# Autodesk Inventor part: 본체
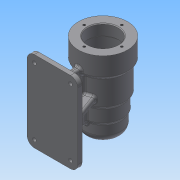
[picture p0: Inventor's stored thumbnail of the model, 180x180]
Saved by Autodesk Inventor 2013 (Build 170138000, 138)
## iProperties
Created: 2016-06
Part Number: 본체
Material: 일반
Document SubType Name: Modeling
Designer: Administrator
Density: 1 g/cm^3
Author: Administrator
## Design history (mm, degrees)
sketch "스케치1"
  geometry: C1 r 34 at (0, 0); 1 further point
  constraints: 1 centre point, 1 coincident
  dimensions: "d0" = 68 diameter of C1
extrude "돌출1" new body sketch "스케치1" distance "d1" = 28; taper "d2" = 0 deg
sketch "스케치2"
  geometry: C1 r 34 at (0, 0) reference; C2 r 30 at (0, 0)
  constraints: 1 centre point, 1 coincident
  dimensions: "d3" = 60 diameter of C2
extrude "돌출2" join sketch "스케치2" distance "d4" = 39; taper "d5" = 0 deg
sketch "스케치3"
  geometry: C1 r 30 at (0, 0) reference; C2 r 27 at (0, 0)
  constraints: 1 centre point, 1 coincident
  dimensions: "d6" = 54 diameter of C2
extrude "돌출3" join sketch "스케치3" distance "d7" = 20; taper "d8" = 0 deg
sketch "스케치4"
  geometry: C1 r 27 at (0, 0) reference; C2 r 25 at (0, 0)
  constraints: 1 centre point, 1 coincident
  dimensions: "d9" = 50 diameter of C2
extrude "돌출4" join sketch "스케치4" distance "d10" = 25; taper "d11" = 0 deg
hole "구멍1" diameter "d14" = 42; stored, may be unused: countersink angle "d18" = 90 deg, drill point angle "d20" = 0 deg; dims "d12" = 10, "d13" = 10, "d15" = 6, "d16" = 4, "d17" = 2, "d19" = 15
hole "구멍2" diameter "d23" = 48; stored, may be unused: countersink angle "d27" = 90 deg, drill point angle "d29" = 0 deg; dims "d21" = 10, "d22" = 10, "d24" = 6, "d25" = 4, "d26" = 2, "d28" = 54
hole "구멍3" diameter "d32" = 42; stored, may be unused: countersink angle "d36" = 90 deg, drill point angle "d38" = 0 deg; dims "d30" = 10, "d31" = 10, "d33" = 6, "d34" = 4, "d35" = 2, "d37" = 12
hole "구멍4" diameter "d41" = 35; stored, may be unused: countersink angle "d45" = 90 deg, drill point angle "d47" = 0 deg; dims "d39" = 10, "d40" = 10, "d42" = 6, "d43" = 4, "d44" = 2, "d46" = 18
hole "구멍5" diameter "d50" = 32; stored, may be unused: countersink angle "d54" = 90 deg, drill point angle "d56" = 0 deg; dims "d48" = 10, "d49" = 10, "d51" = 6, "d52" = 4, "d53" = 2, "d55" = 4
hole "구멍6" diameter "d59" = 21; stored, may be unused: countersink angle "d63" = 90 deg, drill point angle "d65" = 0 deg; dims "d57" = 10, "d58" = 10, "d60" = 6, "d61" = 4, "d62" = 2, "d64" = 3
node "작업 평면1"
sketch "스케치5"
  geometry: L1 (-25, -112)-(25, -112) reference; L2 (-34, 0)-(34, 0) reference; L3 (27.711, -56)-(106.129, -56); L4 (-35, -112)-(35, -112); L5 (35, -112)-(35, 0); L6 (35, 0)-(-35, 0); L7 (-35, 0)-(-35, -112); L8 (-35, -112)-(35, 0); L9 (35, -112)-(-35, 0); 5 further points
  constraints: 14 end point, 5 midpoint, 2 parallel, 1 horizontal, 1 perpendicular, 1 point on line, 1 vertical alignment
  dimensions: "d69" = 56 distance between parallel lines of L3 L1; "d70" = 70 distance of L6.end L5.end; "d72" = 112 distance between parallel lines of L6 L4
extrude "돌출5" join sketch "스케치5" distance "d73" = 10; taper "d74" = 0 deg
fillet "모깎기7" dims "d133" = 3
sketch "스케치6"
  geometry: L1 (-35, 0)-(35, 0) reference; L2 (35, 0)-(35, 112) reference; L3 (4, 20)-(4, 92); L4 (4, 92)-(-4, 92); L5 (-4, 92)-(-4, 20); L6 (-4, 20)-(4, 20); L7 (4, 56)-(-4, 56); L8 (0, 92)-(0, 20); 1 further point
  constraints: 12 end point, 4 midpoint, 2 parallel, 1 perpendicular
  dimensions: "d75" = 8 distance between parallel lines of L5 L3; "d77" = 56 distance between parallel lines of L1 L7; "d79" = 20 distance between parallel lines of L1 L6; "d80" = 35 distance between parallel lines of L2 L8
extrude "돌출6" join sketch "스케치6" stored distance "d81" = 10; taper "d82" = 0 deg
node "작업 평면2"
sketch "스케치7"
  geometry: L1 (-70, 0)-(-70, 10) reference; L2 (-70, 10)-(-39, 10) reference; L3 (-39, 10)-(-39, 40.268) reference; L4 (-31, 40.268)-(-31, 10) reference; L5 (-31, 10)-(0, 10) reference; L6 (0, 10)-(0, 0) reference; L7 (0, 0)-(-70, 0) reference; L8 (-50.509, 44.32)-(-63, 10); L9 (-19.491, 44.32)-(-7, 10); C1 r 24 at (-35, 70) reference; A1 r 30 centre (-35, 70) between (-31, 40.268) and (-39, 40.268) reference; 1 further point
  constraints: 4 end point, 2 point on circle, 2 point on line
  dimensions: "d83" = 110 deg angle of L5 L9; "d84" = 110 deg angle of L2 L8 (= d83); "d85" = 7 distance from line of L8.end L1; "d86" = 7 distance from line of L9.end L6
  node "절단 모서리 투영1"
feature "리브1" dims "d87" = 1, "d88" = 8, "d89" = 0, "d90" = 0, "d91" = 1, "d92" = 1
feature "리브2" dims "d93" = 1, "d94" = 8, "d95" = 0, "d96" = 0, "d97" = 1, "d98" = 1
node "작업 평면3"
sketch "스케치8"
  geometry: L1 (60, -84)-(60, 28) reference; L2 (60, 28)-(70, 28) reference; L3 (70, 28)-(70, -84) reference; L4 (70, -84)-(60, -84) reference; L5 (16, 28)-(16, 2.657) reference; L6 (-16, 28)-(16, 28) reference; L7 (-16, 2.657)-(-16, 28) reference; L8 (0, -3)-(0, -36) reference; 5 further points
  constraints: 1 midpoint, 1 vertical alignment, 5 other
  dimensions: "d99" = 48 distance from line of L6 point (0, -20)
feature "엠보싱1" sketch "스케치8" dims "d100" = 0.5, "d101" = 0
fillet "모깎기1" dims "d102" = 10, "d114" = 0.3
sketch "스케치9"
  geometry: C1 r 21 at (0, 0) reference; 1 further point
  constraints: 1 vertical alignment
  dimensions: "d103" = 26 distance of C1.centre point (0, 26)
hole "구멍7" sketch "스케치9" at (0, 26) diameter "d104" = 3.242; stored, may be unused: countersink angle "d108" = 90 deg, drill point angle "d110" = 118 deg; dims "d105" = 8, "d106" = 4, "d107" = 2, "d109" = 11
sketch "스케치10"
  geometry: A1 r 10 centre (25, 102) between (35, 102) and (25, 112) reference; A2 r 10 centre (-25, 102) between (-25, 112) and (-35, 102) reference; A3 r 10 centre (-25, 10) between (-35, 10) and (-25, 0) reference; A4 r 10 centre (25, 10) between (25, 0) and (35, 10) reference; 5 further points
  constraints: 4 coincident
hole "구멍8" sketch "스케치10" at (25, 102), (25, 10), (-25, 10), (-25, 102) diameter "d115" = 5; stored, may be unused: countersink angle "d119" = 90 deg, drill point angle "d121" = 0 deg; dims "d116" = 8, "d117" = 9, "d118" = 4, "d120" = 11
fillet "모깎기2" dims "d122" = 3
chamfer "모따기1" distance "d123" = 1; stored, may be unused: second distance "d124" = 2, angle "d125" = 45 deg
chamfer "모따기2" distance "d126" = 4; stored, may be unused: second distance "d127" = 2, angle "d128" = 45 deg
fillet "모깎기8" dims "d134" = 3
node "솔리드1"
pattern_circular "원형 패턴1" dims angle "d112" = 360 deg
node "절단 모서리 투영2"
